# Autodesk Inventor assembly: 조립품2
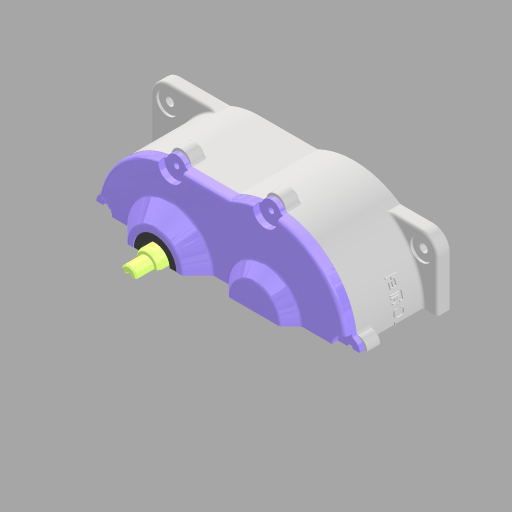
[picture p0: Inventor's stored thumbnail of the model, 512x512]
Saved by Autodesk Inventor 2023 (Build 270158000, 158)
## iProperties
Created: 2025-09
Part Number: 조립품2
Document SubType Name: Assembly
Designer: home
Author: home
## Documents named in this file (18)
- C:\Users\home\Desktop\750903V1004\조립품2.iam
- C:\Users\home\Desktop\750903V1004\본체.ipt
- C:\Users\home\Desktop\750903V1004\커버.ipt
- C:\Users\home\Desktop\750903V1004\오일 실 20 35 8.ipt
- C:\Users\home\Desktop\750903V1004\스러스트 볼 베어링 51102.ipt
- C:\Users\home\Desktop\750903V1004\어댑터.ipt
- C:\Users\home\Desktop\750903V1004\깊은 홈 볼 베어링 6904.ipt
- C:\Users\home\Desktop\750903V1004\슬롯.ipt
- C:\Users\home\Desktop\750903V1004\슬롯 축.ipt
- C:\Users\home\Desktop\750903V1004\평행 키 6x6x14.ipt
- C:\Users\home\Desktop\750903V1004\칼라.ipt
- C:\Users\home\Desktop\750903V1004\6각 구멍붙이 볼트 M6x12.ipt
- C:\Users\home\Desktop\750903V1004\구동 축.ipt
- C:\Users\home\Desktop\750903V1004\구동 휠.ipt
- C:\Users\home\Desktop\750903V1004\캠 플로워.ipt
- C:\Users\home\Desktop\750903V1004\평 와셔 M3.ipt
- C:\Users\home\Desktop\750903V1004\스프링 와셔 M3.ipt
- C:\Users\home\Desktop\750903V1004\육각 너트 M3.ipt
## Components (3 placed, 3 different names)
1. 6각 구멍붙이 볼트 M6x12:1
2. 구동 축:1
3. 구동 휠:1
